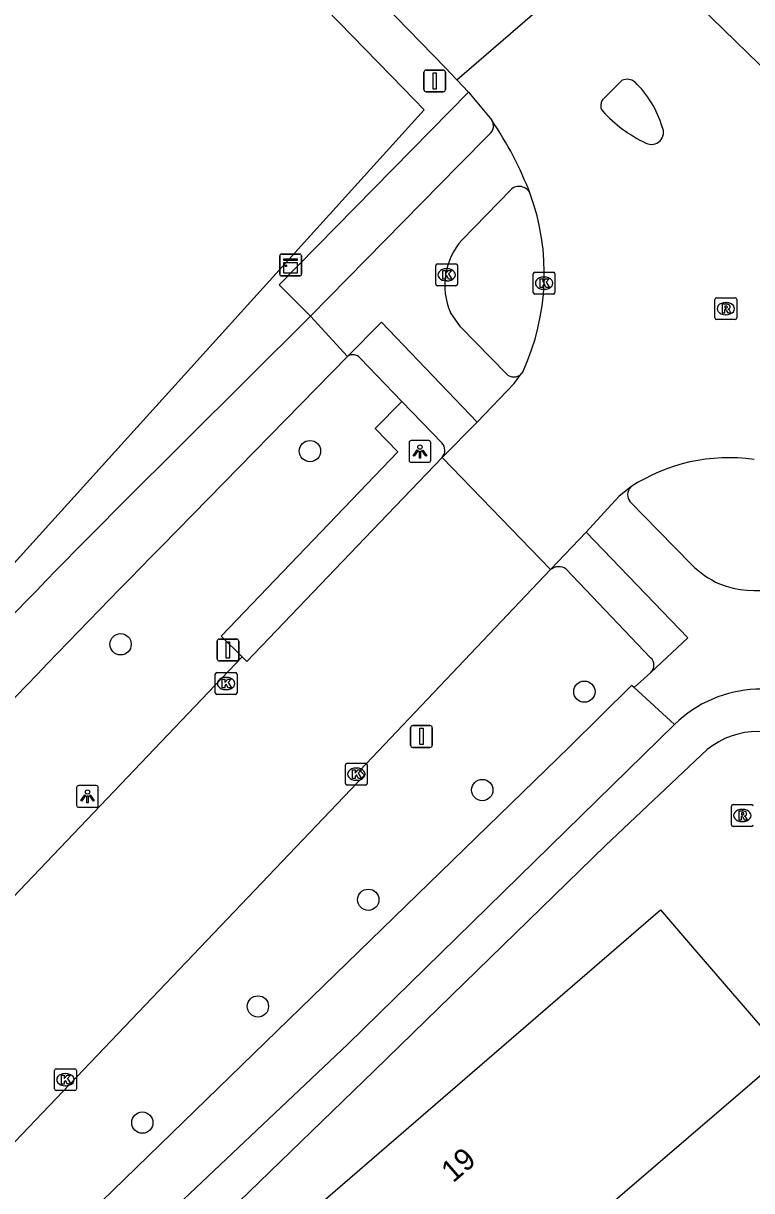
# Model space of a CAD drawing. Extents: x 156141 to 158132, y 385651 to 388399.
# Drawn here: x 156914.8 to 156948.2, y 387219.7 to 387273.3 of the extents above; entities that cross this region are included whole.
import ezdxf

# ---------------------------------------------------------------- set-up
doc = ezdxf.new("R2010")
doc.units = 0
for name, color, linetype in [('IMGEO_Berm_groen', 7, 'Continuous'), ('IMGEO_Boom', 7, 'Continuous'), ('IMGEO_Fietspad_gesloten', 7, 'Continuous'), ('IMGEO_Hek', 7, 'Continuous'), ('IMGEO_Kast', 7, 'Continuous'), ('IMGEO_Kolk', 7, 'Continuous'), ('IMGEO_Lichtpunt', 7, 'Continuous'), ('IMGEO_Pand', 7, 'Continuous'), ('IMGEO_Pand_nummerreeks', 7, 'Continuous'), ('IMGEO_Rijbaan_lokaal_gesloten', 7, 'Continuous'), ('IMGEO_Rioolput', 7, 'Continuous'), ('IMGEO_Verkeersbordpaal', 7, 'Continuous'), ('IMGEO_Voetpad_open', 7, 'Continuous')]:
    doc.layers.add(name, color=color, linetype=linetype)

msp = doc.modelspace()

# ---------------------------------------------------------------- linework, layer by layer
at = {"layer": 'IMGEO_Berm_groen'}
msp.add_lwpolyline([(156902.901, 387235.828), (156933.171, 387269.321), (156932.23, 387270.289), (156921.587, 387281.238), (156915.865, 387288.761), (156908.089, 387303.369), (156905.42, 387307.278), (156895.183, 387318.713)], dxfattribs=at)
at = {"layer": 'IMGEO_Boom'}
for centre in [(156927.938, 387253.644), (156919.246, 387244.778), (156940.528, 387242.602), (156935.842, 387238.084), (156930.613, 387233.046), (156925.548, 387228.149), (156920.246, 387222.815)]:
    msp.add_circle(centre, 0.489, dxfattribs=at)
at = {"layer": 'IMGEO_Fietspad_gesloten'}
for points in [[(156936.171, 387268.195), (156934.772, 387266.775), (156927.959, 387259.837)], [(156934.919, 387263.348), (156937.148, 387265.646)], [(156936.949, 387257.192), (156934.839, 387259.358), (156934.383, 387260.012)], [(156918.092, 387250), (156919.276, 387251.199), (156927.959, 387259.837)], [(156927.959, 387259.837), (156929.655, 387257.991)], [(156929.655, 387257.991), (156931.215, 387259.57), (156935.602, 387254.979)], [(156929.655, 387257.991), (156921.843, 387250), (156921.138, 387249.279)], [(156945.437, 387248.434), (156943.911, 387250), (156942.635, 387251.31)], [(156940.604, 387249.93), (156945.275, 387245.068), (156943.583, 387243.485)], [(156943.583, 387243.485), (156942.815, 387242.786)], [(156942.815, 387242.786), (156942.686, 387242.886), (156939.848, 387240.067), (156915.149, 387216.065)], [(156942.815, 387242.786), (156944.662, 387241.089)], [(156944.662, 387241.089), (156929.678, 387226.421), (156916.847, 387214.277)]]:
    msp.add_lwpolyline(points, dxfattribs=at)
for centre, radius, start, end in [((156935.883, 387268.574), 0.476, 307.2979, 33.6038), ((156937.531, 387265.245), 0.555, 22.6116, 133.6885), ((156937.258, 387261.261), 3.135, 138.2609, 203.4835), ((156937.288, 387257.528), 0.477, 224.7781, 316.3946), ((156943.021, 387251.645), 0.511, 135.8855, 220.9644), ((157231.352, 386940.491), 440.372, 135.34517, 138.02939), ((157246.366, 386927.372), 457.599, 135.29407, 138.03304), ((156948.96, 387252.161), 5.128, 226.609, 244.1628), ((156948.354, 387251.78), 4.538, 248.9549, 314.1294), ((156948.636, 387237.053), 5.665, 50.3333, 134.5554)]:
    msp.add_arc(centre, radius, start, end, dxfattribs=at)
at = {"layer": 'IMGEO_Hek'}
for points in [[(156932.23, 387270.289), (156921.587, 387281.238), (156915.865, 387288.761), (156908.089, 387303.369), (156905.42, 387307.278), (156895.183, 387318.713)], [(156933.171, 387269.321), (156932.23, 387270.289)], [(156901.471, 387234.246), (156933.171, 387269.321)]]:
    msp.add_lwpolyline(points, dxfattribs=at)
at = {"layer": 'IMGEO_Kast'}
for p, q in [((156926.549, 387261.764), (156926.549, 387262.605)), ((156926.549, 387262.605), (156926.549, 387261.764)), ((156926.624, 387262.689), (156927.465, 387262.689)), ((156927.465, 387262.689), (156926.624, 387262.689)), ((156927.549, 387262.614), (156927.549, 387261.773)), ((156927.549, 387261.773), (156927.549, 387262.614)), ((156927.474, 387261.689), (156926.633, 387261.689)), ((156926.633, 387261.689), (156927.474, 387261.689))]:
    msp.add_line(p, q, dxfattribs=at)
for points in [[(156926.744, 387262.479), (156927.344, 387262.479), (156927.344, 387262.394), (156926.744, 387262.394), (156926.744, 387262.479)], [(156926.744, 387262.304), (156927.344, 387262.304), (156927.344, 387261.815), (156926.744, 387261.815), (156926.744, 387262.304)]]:
    msp.add_lwpolyline(points, dxfattribs=at)
msp.add_circle((156926.828, 387262.153), 0.0377, dxfattribs=at)
for centre, start, end in [((156926.627, 387262.611), 92.4484, 184.2845), ((156926.627, 387262.611), 92.4484, 184.2845), ((156927.471, 387262.611), 2.4484, 94.2845), ((156927.471, 387262.611), 2.4484, 94.2845), ((156926.627, 387261.767), 182.4484, 274.2845), ((156926.627, 387261.767), 182.4484, 274.2845), ((156927.471, 387261.767), 272.4484, 4.2845), ((156927.471, 387261.767), 272.4484, 4.2845)]:
    msp.add_arc(centre, 0.0779, start, end, dxfattribs=at)
at = {"layer": 'IMGEO_Kolk'}
for p, q in [((156933.708, 387261.314), (156933.708, 387262.166)), ((156933.783, 387262.24), (156934.635, 387262.24)), ((156934.709, 387262.166), (156934.709, 387261.314)), ((156934.196, 387262.02), (156934.221, 387262.02)), ((156938.179, 387260.93), (156938.179, 387261.782)), ((156938.254, 387261.856), (156939.106, 387261.856)), ((156938.667, 387261.636), (156938.692, 387261.636)), ((156939.18, 387261.782), (156939.18, 387260.93)), ((156934.635, 387261.24), (156933.783, 387261.24)), ((156934.219, 387261.46), (156934.194, 387261.46)), ((156938.69, 387261.076), (156938.665, 387261.076)), ((156939.106, 387260.856), (156938.254, 387260.856)), ((156923.589, 387242.549), (156923.589, 387243.401)), ((156923.664, 387243.475), (156924.516, 387243.475)), ((156924.59, 387243.401), (156924.59, 387242.549)), ((156924.077, 387243.255), (156924.102, 387243.255)), ((156924.516, 387242.475), (156923.664, 387242.475)), ((156924.1, 387242.695), (156924.075, 387242.695)), ((156929.564, 387238.388), (156929.564, 387239.24)), ((156929.639, 387239.314), (156930.491, 387239.314)), ((156930.052, 387239.094), (156930.077, 387239.094)), ((156930.565, 387239.24), (156930.565, 387238.388)), ((156930.075, 387238.534), (156930.05, 387238.534)), ((156930.491, 387238.314), (156929.639, 387238.314)), ((156916.217, 387224.362), (156916.217, 387225.214)), ((156916.292, 387225.288), (156917.144, 387225.288)), ((156917.218, 387225.214), (156917.218, 387224.362)), ((156916.705, 387225.068), (156916.73, 387225.068)), ((156917.144, 387224.288), (156916.292, 387224.288)), ((156916.728, 387224.508), (156916.703, 387224.508))]:
    msp.add_line(p, q, dxfattribs=at)
for points in [[(156933.708, 387261.314), (156933.708, 387262.166)], [(156933.783, 387262.24), (156934.635, 387262.24)], [(156934.709, 387262.166), (156934.709, 387261.314)], [(156934.029, 387261.94), (156934.152, 387261.94), (156934.152, 387261.789), (156934.282, 387261.94), (156934.446, 387261.94), (156934.3, 387261.789), (156934.453, 387261.54), (156934.301, 387261.54), (156934.216, 387261.704), (156934.152, 387261.637), (156934.152, 387261.54), (156934.029, 387261.54), (156934.029, 387261.94)], [(156938.179, 387260.93), (156938.179, 387261.782)], [(156938.254, 387261.856), (156939.106, 387261.856)], [(156938.5, 387261.556), (156938.623, 387261.556), (156938.623, 387261.405), (156938.753, 387261.556), (156938.917, 387261.556), (156938.771, 387261.405), (156938.924, 387261.156), (156938.772, 387261.156), (156938.687, 387261.32), (156938.623, 387261.253), (156938.623, 387261.156), (156938.5, 387261.156), (156938.5, 387261.556)], [(156939.18, 387261.782), (156939.18, 387260.93)], [(156934.635, 387261.24), (156933.783, 387261.24)], [(156939.106, 387260.856), (156938.254, 387260.856)], [(156923.589, 387242.549), (156923.589, 387243.401)], [(156923.664, 387243.475), (156924.516, 387243.475)], [(156924.59, 387243.401), (156924.59, 387242.549)], [(156923.91, 387243.175), (156924.033, 387243.175), (156924.033, 387243.024), (156924.163, 387243.175), (156924.327, 387243.175), (156924.181, 387243.024), (156924.334, 387242.775), (156924.182, 387242.775), (156924.097, 387242.939), (156924.033, 387242.872), (156924.033, 387242.775), (156923.91, 387242.775), (156923.91, 387243.175)], [(156924.516, 387242.475), (156923.664, 387242.475)], [(156929.564, 387238.388), (156929.564, 387239.24)], [(156929.639, 387239.314), (156930.491, 387239.314)], [(156929.885, 387239.014), (156930.008, 387239.014), (156930.008, 387238.863), (156930.138, 387239.014), (156930.302, 387239.014), (156930.156, 387238.863), (156930.309, 387238.614), (156930.157, 387238.614), (156930.072, 387238.778), (156930.008, 387238.711), (156930.008, 387238.614), (156929.885, 387238.614), (156929.885, 387239.014)], [(156930.565, 387239.24), (156930.565, 387238.388)], [(156930.491, 387238.314), (156929.639, 387238.314)], [(156916.217, 387224.362), (156916.217, 387225.214)], [(156916.292, 387225.288), (156917.144, 387225.288)], [(156917.218, 387225.214), (156917.218, 387224.362)], [(156916.538, 387224.988), (156916.661, 387224.988), (156916.661, 387224.837), (156916.791, 387224.988), (156916.955, 387224.988), (156916.809, 387224.837), (156916.962, 387224.588), (156916.81, 387224.588), (156916.725, 387224.752), (156916.661, 387224.685), (156916.661, 387224.588), (156916.538, 387224.588), (156916.538, 387224.988)], [(156917.144, 387224.288), (156916.292, 387224.288)]]:
    msp.add_lwpolyline(points, dxfattribs=at)
for centre, start, end in [((156933.785, 387262.164), 91.552, 178.448), ((156933.785, 387262.164), 91.552, 178.448), ((156934.633, 387262.164), 1.552, 88.448), ((156934.633, 387262.164), 1.552, 88.448), ((156938.256, 387261.78), 91.552, 178.448), ((156938.256, 387261.78), 91.552, 178.448), ((156939.104, 387261.78), 1.552, 88.448), ((156939.104, 387261.78), 1.552, 88.448), ((156933.785, 387261.316), 181.552, 268.448), ((156933.785, 387261.316), 181.552, 268.448), ((156934.633, 387261.316), 271.552, 358.448), ((156934.633, 387261.316), 271.552, 358.448), ((156938.256, 387260.932), 181.552, 268.448), ((156938.256, 387260.932), 181.552, 268.448), ((156939.104, 387260.932), 271.552, 358.448), ((156939.104, 387260.932), 271.552, 358.448), ((156923.666, 387243.399), 91.552, 178.448), ((156923.666, 387243.399), 91.552, 178.448), ((156924.514, 387243.399), 1.552, 88.448), ((156924.514, 387243.399), 1.552, 88.448), ((156923.666, 387242.551), 181.552, 268.448), ((156923.666, 387242.551), 181.552, 268.448), ((156924.514, 387242.551), 271.552, 358.448), ((156924.514, 387242.551), 271.552, 358.448), ((156929.641, 387239.238), 91.552, 178.448), ((156929.641, 387239.238), 91.552, 178.448), ((156930.489, 387239.238), 1.552, 88.448), ((156930.489, 387239.238), 1.552, 88.448), ((156929.641, 387238.39), 181.552, 268.448), ((156929.641, 387238.39), 181.552, 268.448), ((156930.489, 387238.39), 271.552, 358.448), ((156930.489, 387238.39), 271.552, 358.448), ((156916.294, 387225.212), 91.552, 178.448), ((156916.294, 387225.212), 91.552, 178.448), ((156917.142, 387225.212), 1.552, 88.448), ((156917.142, 387225.212), 1.552, 88.448), ((156916.294, 387224.364), 181.552, 268.448), ((156916.294, 387224.364), 181.552, 268.448), ((156917.142, 387224.364), 271.552, 358.448), ((156917.142, 387224.364), 271.552, 358.448)]:
    msp.add_arc(centre, 0.0765, start, end, dxfattribs=at)
for centre, major_axis, ratio, start_param, end_param in [((156934.195, 387261.74), (-0.387, 0.002), 0.722429, 4.712389, 7.853982), ((156934.22, 387261.74), (-0.39, 0.002), 0.717154, 1.570796, 4.712389), ((156938.666, 387261.356), (-0.387, 0.002), 0.722429, 4.712389, 7.853982), ((156938.691, 387261.356), (-0.39, 0.002), 0.717154, 1.570796, 4.712389), ((156924.076, 387242.975), (-0.387, 0.002), 0.722429, 4.712389, 7.853982), ((156924.101, 387242.975), (-0.39, 0.002), 0.717154, 1.570796, 4.712389), ((156930.051, 387238.814), (-0.387, 0.002), 0.722429, 4.712389, 7.853982), ((156930.076, 387238.814), (-0.39, 0.002), 0.717154, 1.570796, 4.712389), ((156916.704, 387224.788), (-0.387, 0.002), 0.722429, 4.712389, 7.853982), ((156916.729, 387224.788), (-0.39, 0.002), 0.717154, 1.570796, 4.712389)]:
    msp.add_ellipse(centre, major_axis=major_axis, ratio=ratio, start_param=start_param, end_param=end_param, dxfattribs=at)
at = {"layer": 'IMGEO_Lichtpunt'}
for p, q in [((156932.486, 387254.033), (156932.486, 387253.226)), ((156932.486, 387254.033), (156932.486, 387253.226)), ((156933.388, 387254.128), (156932.58, 387254.128)), ((156933.388, 387254.128), (156932.58, 387254.128)), ((156933.482, 387253.226), (156933.482, 387254.033)), ((156933.482, 387253.226), (156933.482, 387254.033)), ((156932.58, 387253.132), (156933.388, 387253.132)), ((156932.58, 387253.132), (156933.388, 387253.132)), ((156917.231, 387238.197), (156917.231, 387237.39)), ((156917.231, 387238.197), (156917.231, 387237.39)), ((156918.133, 387238.292), (156917.325, 387238.292)), ((156918.133, 387238.292), (156917.325, 387238.292)), ((156918.227, 387237.39), (156918.227, 387238.197)), ((156918.227, 387237.39), (156918.227, 387238.197)), ((156917.325, 387237.296), (156918.133, 387237.296)), ((156917.325, 387237.296), (156918.133, 387237.296))]:
    msp.add_line(p, q, dxfattribs=at)
for points in [[(156932.86, 387253.697), (156932.899, 387253.669), (156932.711, 387253.407), (156932.673, 387253.434), (156932.86, 387253.697)], [(156932.962, 387253.649), (156933.009, 387253.649), (156933.009, 387253.327), (156932.962, 387253.327), (156932.962, 387253.649)], [(156933.072, 387253.669), (156933.11, 387253.696), (156933.297, 387253.434), (156933.258, 387253.406), (156933.072, 387253.669)], [(156917.605, 387237.861), (156917.644, 387237.833), (156917.456, 387237.571), (156917.418, 387237.598), (156917.605, 387237.861)], [(156917.707, 387237.813), (156917.754, 387237.813), (156917.754, 387237.491), (156917.707, 387237.491), (156917.707, 387237.813)], [(156917.817, 387237.833), (156917.855, 387237.86), (156918.042, 387237.598), (156918.003, 387237.57), (156917.817, 387237.833)]]:
    msp.add_lwpolyline(points, dxfattribs=at)
for centre in [(156932.985, 387253.831), (156917.73, 387237.995)]:
    msp.add_circle(centre, 0.0994, dxfattribs=at)
for centre, start, end in [((156932.58, 387254.033), 90, 180), ((156932.58, 387254.033), 90, 180), ((156933.388, 387254.033), 0, 90), ((156933.388, 387254.033), 0, 90), ((156932.58, 387253.226), 180, 270), ((156932.58, 387253.226), 180, 270), ((156933.388, 387253.226), 270, 0), ((156933.388, 387253.226), 270, 360), ((156917.325, 387238.197), 90, 180), ((156917.325, 387238.197), 90, 180), ((156918.133, 387238.197), 0, 90), ((156918.133, 387238.197), 0, 90), ((156917.325, 387237.39), 180, 270), ((156917.325, 387237.39), 180, 270), ((156918.133, 387237.39), 270, 0), ((156918.133, 387237.39), 270, 360)]:
    msp.add_arc(centre, 0.0946, start, end, dxfattribs=at)
at = {"layer": 'IMGEO_Pand'}
msp.add_lwpolyline([(156927.567, 387206.666), (156925.061, 387209.582), (156921.803, 387213.375), (156944.024, 387232.591), (156945.403, 387230.986), (156949.741, 387225.937), (156940.871, 387218.316), (156943.138, 387215.677), (156942.484, 387215.115), (156943.076, 387214.426), (156941.726, 387213.266), (156941.168, 387213.916), (156939.147, 387212.18), (156936.955, 387214.732), (156927.567, 387206.666)], dxfattribs=at)
at = {"layer": 'IMGEO_Rijbaan_lokaal_gesloten'}
for points in [[(156922.275, 387283.474), (156934.143, 387271.257), (156934.676, 387270.694)], [(156934.676, 387270.694), (156942.293, 387277.28)], [(156943.639, 387276.201), (156961.662, 387258.661)], [(156935.208, 387270.131), (156934.676, 387270.694)], [(156942.257, 387270.67), (156941.414, 387269.834)], [(156935.208, 387270.131), (156936.279, 387268.837)], [(156937.713, 387257.312), (156937.633, 387257.199)], [(156935.602, 387254.979), (156937.31, 387256.743), (156937.633, 387257.199)], [(156935.602, 387254.979), (156934, 387253.346)], [(156934, 387253.346), (156930.798, 387250), (156925.047, 387243.989), (156924.829, 387244.202)], [(156938.979, 387248.204), (156934, 387253.346)], [(156942.654, 387252.001), (156942.102, 387251.556), (156940.604, 387249.93)], [(156938.979, 387248.204), (156940.604, 387249.93)], [(156911.876, 387219.298), (156930.437, 387238.77), (156930.223, 387238.975), (156938.979, 387248.204)], [(156924.829, 387244.202), (156913.363, 387232.176), (156912.298, 387231.059)]]:
    msp.add_lwpolyline(points, dxfattribs=at)
for centre, radius, start, end in [((156942.484, 387270.122), 0.594, 52.4222, 112.4904), ((156939.504, 387267.144), 4.802, 16.8051, 45.8964), ((156941.708, 387269.517), 0.432, 132.8674, 215.9105), ((156946.136, 387273.631), 6.473, 222.4311, 244.54), ((156922.426, 387259.45), 16.734, 21.0394, 34.1207), ((156943.608, 387268.279), 0.554, 242.6707, 27.0991), ((156927.944, 387261.789), 10.746, 335.3804, 19.9659), ((156947.168, 387245.091), 8.253, 82.0365, 123.154)]:
    msp.add_arc(centre, radius, start, end, dxfattribs=at)
at = {"layer": 'IMGEO_Rioolput'}
for p, q in [((156946.519, 387259.76), (156946.519, 387260.612)), ((156946.594, 387260.686), (156947.446, 387260.686)), ((156947.007, 387260.466), (156947.032, 387260.466)), ((156947.52, 387260.612), (156947.52, 387259.76)), ((156947.446, 387259.686), (156946.594, 387259.686)), ((156947.03, 387259.906), (156947.005, 387259.906)), ((156947.351, 387237.415), (156948.203, 387237.415)), ((156947.276, 387236.489), (156947.276, 387237.341)), ((156947.764, 387237.195), (156947.789, 387237.195)), ((156948.203, 387236.415), (156947.351, 387236.415)), ((156947.787, 387236.635), (156947.762, 387236.635))]:
    msp.add_line(p, q, dxfattribs=at)
for points in [[(156946.519, 387259.76), (156946.519, 387260.612)], [(156946.594, 387260.686), (156947.446, 387260.686)], [(156947.52, 387260.612), (156947.52, 387259.76)], [(156947.108, 387260.384), (156946.856, 387260.386), (156946.856, 387259.986)], [(156946.856, 387259.986), (156946.98, 387259.986), (156946.98, 387260.148), (156946.991, 387260.148)], [(156947.034, 387260.305), (156946.98, 387260.305), (156946.98, 387260.224)], [(156946.98, 387260.224), (156947.032, 387260.224)], [(156947.038, 387260.119), (156947.109, 387259.986), (156947.249, 387259.986), (156947.184, 387260.112)], [(156947.446, 387259.686), (156946.594, 387259.686)], [(156947.351, 387237.415), (156948.203, 387237.415)], [(156947.276, 387236.489), (156947.276, 387237.341)], [(156947.865, 387237.113), (156947.613, 387237.115), (156947.613, 387236.715)], [(156947.613, 387236.715), (156947.737, 387236.715), (156947.737, 387236.877), (156947.748, 387236.877)], [(156947.791, 387237.034), (156947.737, 387237.034), (156947.737, 387236.953)], [(156947.737, 387236.953), (156947.789, 387236.953)], [(156948.203, 387236.415), (156947.351, 387236.415)], [(156947.795, 387236.848), (156947.866, 387236.715), (156948.006, 387236.715), (156947.941, 387236.841)]]:
    msp.add_lwpolyline(points, dxfattribs=at)
for centre, radius, start, end in [((156946.596, 387260.61), 0.0765, 91.552, 178.448), ((156946.596, 387260.61), 0.0765, 91.552, 178.448), ((156947.444, 387260.61), 0.0765, 1.552, 88.448), ((156947.444, 387260.61), 0.0765, 1.552, 88.448), ((156946.99, 387260.095), 0.0533, 26.0293, 88.6989), ((156947.016, 387260.413), 0.19, 274.7715, 282.9687), ((156947.04, 387260.209), 0.0964, 77.0061, 93.1865), ((156947.054, 387260.266), 0.0378, 276.6634, 79.6772), ((156947.107, 387260.274), 0.109, 350.3612, 89.416), ((156947.105, 387260.274), 0.112, 277.5842, 350.9817), ((156947.089, 387260.059), 0.108, 29.5134, 73.7905), ((156946.596, 387259.762), 0.0765, 181.552, 268.448), ((156946.596, 387259.762), 0.0765, 181.552, 268.448), ((156947.444, 387259.762), 0.0765, 271.552, 358.448), ((156947.444, 387259.762), 0.0765, 271.552, 358.448), ((156947.353, 387237.339), 0.0765, 91.552, 178.448), ((156947.353, 387237.339), 0.0765, 91.552, 178.448), ((156948.201, 387237.339), 0.0765, 1.552, 88.448), ((156948.201, 387237.339), 0.0765, 1.552, 88.448), ((156947.747, 387236.824), 0.0533, 26.0293, 88.6989), ((156947.773, 387237.142), 0.19, 274.7715, 282.9687), ((156947.797, 387236.938), 0.0964, 77.0061, 93.1865), ((156947.811, 387236.995), 0.0378, 276.6634, 79.6772), ((156947.864, 387237.003), 0.109, 350.3612, 89.416), ((156947.862, 387237.003), 0.112, 277.5842, 350.9817), ((156947.846, 387236.788), 0.108, 29.5134, 73.7905), ((156947.353, 387236.491), 0.0765, 181.552, 268.448), ((156947.353, 387236.491), 0.0765, 181.552, 268.448), ((156948.201, 387236.491), 0.0765, 271.552, 358.448), ((156948.201, 387236.491), 0.0765, 271.552, 358.448)]:
    msp.add_arc(centre, radius, start, end, dxfattribs=at)
for centre, major_axis, ratio, start_param, end_param in [((156947.006, 387260.186), (-0.387, 0.002), 0.722429, 4.712389, 7.853982), ((156947.031, 387260.186), (-0.39, 0.002), 0.717154, 1.570796, 4.712389), ((156947.763, 387236.915), (-0.387, 0.002), 0.722429, 4.712389, 7.853982), ((156947.788, 387236.915), (-0.39, 0.002), 0.717154, 1.570796, 4.712389)]:
    msp.add_ellipse(centre, major_axis=major_axis, ratio=ratio, start_param=start_param, end_param=end_param, dxfattribs=at)
at = {"layer": 'IMGEO_Verkeersbordpaal'}
for p, q in [((156933.163, 387270.24), (156933.163, 387271.04)), ((156933.163, 387271.04), (156933.163, 387270.24)), ((156933.263, 387271.14), (156934.053, 387271.14)), ((156934.053, 387271.14), (156933.263, 387271.14)), ((156934.153, 387271.04), (156934.153, 387270.24)), ((156934.153, 387270.24), (156934.153, 387271.04)), ((156934.053, 387270.14), (156933.263, 387270.14)), ((156933.263, 387270.14), (156934.053, 387270.14)), ((156923.677, 387244.115), (156923.677, 387244.915)), ((156923.677, 387244.915), (156923.677, 387244.115)), ((156923.777, 387245.015), (156924.567, 387245.015)), ((156924.567, 387245.015), (156923.777, 387245.015)), ((156924.667, 387244.915), (156924.667, 387244.115)), ((156924.667, 387244.115), (156924.667, 387244.915)), ((156924.567, 387244.015), (156923.777, 387244.015)), ((156923.777, 387244.015), (156924.567, 387244.015)), ((156932.555, 387240.144), (156932.555, 387240.944)), ((156932.555, 387240.944), (156932.555, 387240.144)), ((156932.655, 387241.044), (156933.445, 387241.044)), ((156933.445, 387241.044), (156932.655, 387241.044)), ((156933.545, 387240.944), (156933.545, 387240.144)), ((156933.545, 387240.144), (156933.545, 387240.944)), ((156933.445, 387240.044), (156932.655, 387240.044)), ((156932.655, 387240.044), (156933.445, 387240.044))]:
    msp.add_line(p, q, dxfattribs=at)
for points in [[(156933.583, 387271.015), (156933.733, 387271.015), (156933.733, 387270.265), (156933.583, 387270.265), (156933.583, 387271.015)], [(156924.097, 387244.89), (156924.247, 387244.89), (156924.247, 387244.14), (156924.097, 387244.14), (156924.097, 387244.89)], [(156932.975, 387240.919), (156933.125, 387240.919), (156933.125, 387240.169), (156932.975, 387240.169), (156932.975, 387240.919)]]:
    msp.add_lwpolyline(points, dxfattribs=at)
for centre, start, end in [((156933.263, 387271.04), 90, 180), ((156933.263, 387271.04), 90, 180), ((156934.053, 387271.04), 0, 90), ((156934.053, 387271.04), 360, 90), ((156933.263, 387270.24), 180, 270), ((156933.263, 387270.24), 180, 270), ((156934.053, 387270.24), 270, 0), ((156934.053, 387270.24), 270, 0), ((156923.777, 387244.915), 90, 180), ((156923.777, 387244.915), 90, 180), ((156924.567, 387244.915), 0, 90), ((156924.567, 387244.915), 360, 90), ((156923.777, 387244.115), 180, 270), ((156923.777, 387244.115), 180, 270), ((156924.567, 387244.115), 270, 0), ((156924.567, 387244.115), 270, 0), ((156932.655, 387240.944), 90, 180), ((156932.655, 387240.944), 90, 180), ((156933.445, 387240.944), 0, 90), ((156933.445, 387240.944), 360, 90), ((156932.655, 387240.144), 180, 270), ((156932.655, 387240.144), 180, 270), ((156933.445, 387240.144), 270, 0), ((156933.445, 387240.144), 270, 0)]:
    msp.add_arc(centre, 0.1, start, end, dxfattribs=at)
at = {"layer": 'IMGEO_Voetpad_open'}
for points in [[(156927.959, 387259.837), (156926.524, 387261.286), (156935.208, 387270.131)], [(156932.159, 387255.922), (156930.243, 387257.914)], [(156924.829, 387244.202), (156923.857, 387245.154), (156931.968, 387253.616), (156930.922, 387254.686), (156932.159, 387255.922)], [(156933.984, 387254.026), (156932.159, 387255.922)], [(156939.693, 387248.232), (156943.569, 387244.157)], [(156918.427, 387213.133), (156930.882, 387225.197), (156941.498, 387235.541), (156946.157, 387239.942)]]:
    msp.add_lwpolyline(points, dxfattribs=at)
for centre, radius, start, end in [((156929.908, 387257.636), 0.436, 39.6494, 125.4295), ((156933.628, 387253.677), 0.498, 318.3284, 44.3674), ((156939.354, 387247.752), 0.588, 54.7962, 129.6953), ((156943.256, 387243.814), 0.464, 314.7963, 47.5907), ((156948.493, 387237.082), 3.693, 50.9764, 129.2449)]:
    msp.add_arc(centre, radius, start, end, dxfattribs=at)

# ---------------------------------------------------------------- texts
at = {"layer": 'IMGEO_Pand_nummerreeks'}
msp.add_text('19', height=1, rotation=40.8522, dxfattribs=at).set_placement((156934.503, 387220.021))

doc.saveas('drawing.dxf')
